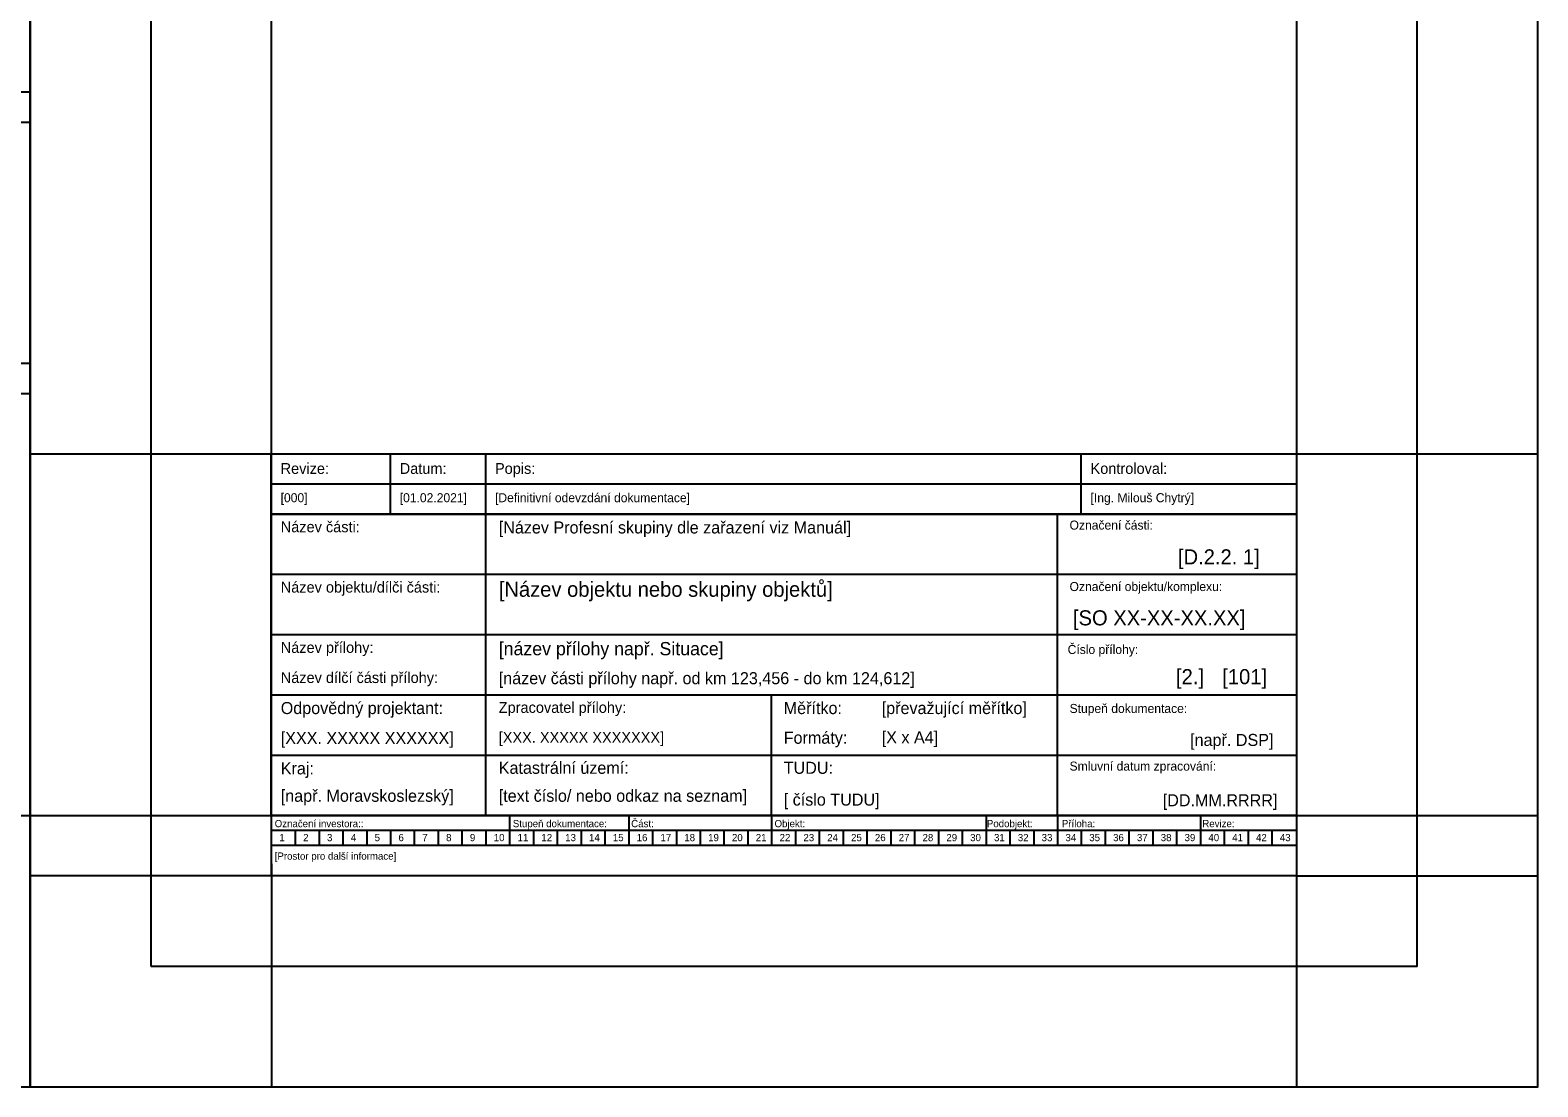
# Model space of a CAD drawing. Extents: x -34.3 to 48, y 36.7 to 71.8.
# Drawn here: x 23 to 48, y 36.73 to 54.26 of the extents above; entities that cross this region are included whole.
import ezdxf

# ---------------------------------------------------------------- set-up
doc = ezdxf.new("R2010")
doc.units = 0
for name, color, linetype in [('Default', 7, 'Continuous'), ('Rozpiska_pole_1', 7, 'Continuous'), ('Rozpiska_pole_4', 7, 'Continuous'), ('Rozpiska_pole_7', 7, 'Continuous'), ('Rozpiska_pole_8', 7, 'Continuous')]:
    doc.layers.add(name, color=color, linetype=linetype)

msp = doc.modelspace()

# ---------------------------------------------------------------- linework, layer by layer
at = {"layer": 'Default'}
for p, q in [((-2, 53.234), (23, 53.234)), ((-2, 52.734), (23, 52.734)), ((-2, 48.734), (23, 48.734)), ((-2, 48.234), (23, 48.234)), ((23, 47.234), (47.999, 47.234)), ((-2, 41.234), (23, 41.234)), ((23, 41.234), (48, 41.234)), ((27, 40.434), (27, 36.734)), ((44, 40.434), (44, 36.734)), ((27, 40.234), (23, 40.234)), ((44, 40.234), (48, 40.234))]:
    msp.add_line(p, q, dxfattribs=at)
for points in [[(-2, 36.734), (23, 36.734), (23, 70.434), (-2, 70.434)], [(23, 36.734), (48, 36.734), (48, 70.434), (23, 70.434)], [(25, 38.734), (46, 38.734), (46, 68.434), (25, 68.434)]]:
    msp.add_lwpolyline(points, close=True, dxfattribs=at)
at = {"layer": 'Rozpiska_pole_1'}
msp.add_lwpolyline([(27, 66.734), (44, 66.734), (44, 40.234), (27, 40.234)], close=True, dxfattribs=at)
at = {"layer": 'Rozpiska_pole_4'}
for p, q in [((28.974, 46.234), (28.974, 47.234)), ((30.554, 46.234), (30.554, 47.234)), ((40.429, 46.234), (40.429, 47.234)), ((26.999, 46.734), (43.999, 46.734))]:
    msp.add_line(p, q, dxfattribs=at)
msp.add_lwpolyline([(26.999, 47.234), (43.999, 47.234), (43.999, 46.234), (26.999, 46.234)], close=True, dxfattribs=at)
at = {"layer": 'Rozpiska_pole_7'}
for p, q in [((27, 46.234), (40.035, 46.234)), ((30.555, 41.234), (30.555, 46.234)), ((40.035, 46.234), (44, 46.234)), ((27, 45.234), (40.035, 45.234)), ((40.035, 45.234), (44, 45.234)), ((27, 44.234), (40.035, 44.234)), ((40.035, 44.234), (44, 44.234)), ((27, 43.234), (30.555, 43.234)), ((30.555, 43.234), (43.999, 43.234)), ((35.295, 41.234), (35.295, 43.234)), ((27, 42.234), (43.999, 42.234))]:
    msp.add_line(p, q, dxfattribs=at)
msp.add_lwpolyline([(26.999, 46.234), (43.999, 46.234), (43.999, 41.234), (26.999, 41.234)], close=True, dxfattribs=at)
msp.add_lwpolyline([(44, 46.234), (44, 41.234), (40.035, 41.234), (40.035, 46.234)], dxfattribs=at)
at = {"layer": 'Rozpiska_pole_8'}
for p, q in [((30.95, 41.234), (30.95, 40.734)), ((32.925, 41.234), (32.925, 40.734)), ((35.295, 41.234), (35.295, 40.734)), ((38.85, 41.234), (38.85, 40.734)), ((40.035, 41.234), (40.035, 40.734)), ((42.405, 41.234), (42.405, 40.734)), ((44, 40.984), (27, 40.984)), ((27.395, 40.984), (27.395, 40.734)), ((27.79, 40.984), (27.79, 40.734)), ((28.185, 40.984), (28.185, 40.734)), ((28.58, 40.984), (28.58, 40.734)), ((28.975, 40.984), (28.975, 40.734)), ((29.37, 40.984), (29.37, 40.734)), ((29.765, 40.984), (29.765, 40.734)), ((30.16, 40.984), (30.16, 40.734)), ((30.555, 40.984), (30.555, 40.734)), ((31.345, 40.984), (31.345, 40.734)), ((31.74, 40.984), (31.74, 40.734)), ((32.135, 40.984), (32.135, 40.734)), ((32.53, 40.984), (32.53, 40.734)), ((33.32, 40.984), (33.32, 40.734)), ((33.715, 40.984), (33.715, 40.734)), ((34.11, 40.984), (34.11, 40.734)), ((34.505, 40.984), (34.505, 40.734)), ((34.9, 40.984), (34.9, 40.734)), ((35.69, 40.984), (35.69, 40.734)), ((36.085, 40.984), (36.085, 40.734)), ((36.48, 40.984), (36.48, 40.734)), ((36.875, 40.984), (36.875, 40.734)), ((37.27, 40.984), (37.27, 40.734)), ((37.665, 40.984), (37.665, 40.734)), ((38.06, 40.984), (38.06, 40.734)), ((38.455, 40.984), (38.455, 40.734)), ((39.245, 40.984), (39.245, 40.734)), ((39.64, 40.984), (39.64, 40.734)), ((40.43, 40.984), (40.43, 40.734)), ((40.825, 40.984), (40.825, 40.734)), ((41.22, 40.984), (41.22, 40.734)), ((41.615, 40.984), (41.615, 40.734)), ((42.01, 40.984), (42.01, 40.734)), ((42.8, 40.984), (42.8, 40.734)), ((43.195, 40.984), (43.195, 40.734)), ((43.59, 40.984), (43.59, 40.734))]:
    msp.add_line(p, q, dxfattribs=at)
msp.add_lwpolyline([(27, 41.234), (44, 41.234), (44, 40.734), (27, 40.734)], close=True, dxfattribs=at)

# ---------------------------------------------------------------- texts
at = {"layer": 'Rozpiska_pole_4'}
for s, height, p in [('Revize:', 0.18, (27.153, 46.899)), ('Datum:', 0.18, (29.128, 46.899)), ('Popis:', 0.18, (30.708, 46.899)), ('Kontroloval:', 0.18, (40.583, 46.899)), ('[000]', 0.15, (27.153, 46.429)), ('[01.02.2021]', 0.15, (29.128, 46.429)), ('[Definitivní odevzdání dokumentace]', 0.15, (30.708, 46.429)), ('[Ing. Milouš Chytrý]', 0.15, (40.583, 46.429))]:
    msp.add_text(s, height=height, dxfattribs=at).set_placement(p)
at = {"layer": 'Rozpiska_pole_7'}
for s, height, p in [('Název části:', 0.18, (27.155, 45.931)), ('[Název Profesní skupiny dle zařazení viz Manuál]', 0.2, (30.77, 45.911)), ('Označení části:', 0.15, (40.235, 45.975)), ('[D.2.2. 1]', 0.25, (42.032, 45.398)), ('Název objektu/dílči části:', 0.18, (27.155, 44.931)), ('[Název objektu nebo skupiny objektů]', 0.25, (30.77, 44.861)), ('Označení objektu/komplexu:', 0.15, (40.235, 44.956)), ('[SO XX-XX-XX.XX]', 0.25, (40.291, 44.387)), ('Název přílohy:', 0.18, (27.155, 43.931)), ('[název přílohy např. Situace]', 0.22, (30.77, 43.891)), ('Číslo přílohy:', 0.15, (40.203, 43.912)), ('Název dílčí části přílohy:', 0.18, (27.155, 43.431)), ('[název části přílohy např. od km 123,456 - do km 124,612]', 0.2, (30.77, 43.411)), ('[2.]', 0.25, (42, 43.412)), ('[101]', 0.25, (42.767, 43.412)), ('Odpovědný projektant:', 0.2, (27.155, 42.916)), ('Zpracovatel přílohy:', 0.18, (30.77, 42.936)), ('Měřítko:', 0.2, (35.495, 42.916)), ('[převažující měřítko]', 0.2, (37.12, 42.916)), ('Stupeň dokumentace:', 0.15, (40.235, 42.934)), ('[XXX. XXXXX XXXXXX]', 0.2, (27.155, 42.42)), ('[XXX. XXXXX XXXXXXX]', 0.18, (30.77, 42.44)), ('Formáty:', 0.2, (35.495, 42.424)), ('[X x A4]', 0.2, (37.12, 42.431)), ('[např. DSP]', 0.2, (42.234, 42.387)), ('Kraj:', 0.2, (27.155, 41.916)), ('Katastrální území:', 0.2, (30.77, 41.925)), ('TUDU:', 0.2, (35.495, 41.925)), ('Smluvní datum zpracování:', 0.15, (40.235, 41.978)), ('[např. Moravskoslezský]', 0.2, (27.155, 41.461)), ('[text číslo/ nebo odkaz na seznam]', 0.2, (30.77, 41.461)), ('[ číslo TUDU]', 0.2, (35.495, 41.398)), ('[DD.MM.RRRR]', 0.2, (41.78, 41.387))]:
    msp.add_text(s, height=height, dxfattribs=at).set_placement(p)
at = {"layer": 'Rozpiska_pole_8'}
for s, p in [('Označení investora::', (27.055, 41.04)), ('Stupeň dokumentace:', (31.003, 41.04)), ('Část:', (32.966, 41.04)), ('Objekt:', (35.343, 41.04)), ('Podobjekt:', (38.864, 41.04)), ('Příloha:', (40.107, 41.04)), ('Revize:', (42.436, 41.04)), ('1', (27.132, 40.808)), ('2', (27.527, 40.808)), ('3', (27.922, 40.808)), ('4', (28.317, 40.808)), ('5', (28.712, 40.808)), ('6', (29.107, 40.808)), ('7', (29.502, 40.808)), ('8', (29.897, 40.808)), ('9', (30.292, 40.808)), ('10', (30.687, 40.808)), ('11', (31.082, 40.808)), ('12', (31.477, 40.808)), ('13', (31.872, 40.808)), ('14', (32.267, 40.808)), ('15', (32.662, 40.808)), ('16', (33.057, 40.808)), ('17', (33.452, 40.808)), ('18', (33.847, 40.808)), ('19', (34.242, 40.808)), ('20', (34.637, 40.808)), ('21', (35.032, 40.808)), ('22', (35.427, 40.808)), ('23', (35.822, 40.808)), ('24', (36.217, 40.808)), ('25', (36.612, 40.808)), ('26', (37.007, 40.808)), ('27', (37.402, 40.808)), ('28', (37.797, 40.808)), ('29', (38.192, 40.808)), ('30', (38.587, 40.808)), ('31', (38.982, 40.808)), ('32', (39.377, 40.808)), ('33', (39.772, 40.808)), ('34', (40.167, 40.808)), ('35', (40.562, 40.808)), ('36', (40.957, 40.808)), ('37', (41.352, 40.808)), ('38', (41.747, 40.808)), ('39', (42.142, 40.808)), ('40', (42.537, 40.808)), ('41', (42.932, 40.808)), ('42', (43.327, 40.808)), ('43', (43.722, 40.808)), ('[Prostor pro další informace]', (27.055, 40.501))]:
    msp.add_text(s, height=0.12, dxfattribs=at).set_placement(p)

doc.saveas('drawing.dxf')
